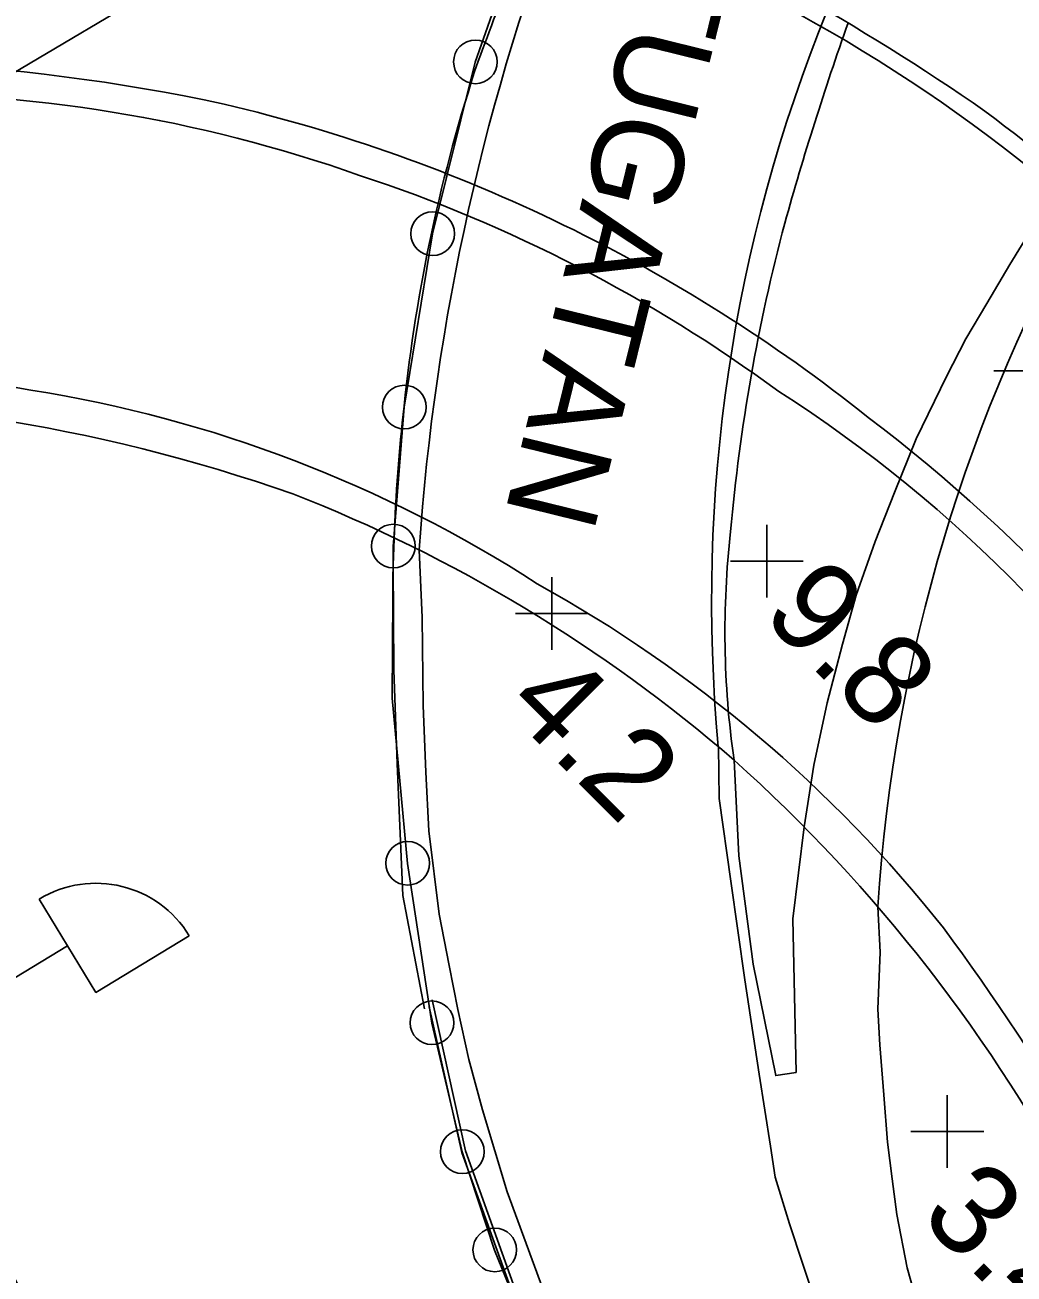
# Model space of a CAD drawing. Extents: x 1596643 to 1597288, y 13057194 to 13057957.
# Drawn here: x 1596899.03 to 1596926.19, y 13057506.23 to 13057540.55 of the extents above; entities that cross this region are included whole.
import ezdxf

# ---------------------------------------------------------------- set-up
doc = ezdxf.new("R2010")
doc.units = 0
for name, color, linetype in [('A spårmitt L', 7, 'Continuous'), ('BAS bro ej def L', 7, 'Continuous'), ('BAS byggnad anläggning L', 7, 'Continuous'), ('BAS gränspunkt P', 7, 'Continuous'), ('BAS Level 16', 7, 'Continuous'), ('BAS Level 37', 7, 'Continuous'), ('BAS markytetext T', 7, 'Continuous'), ('BAS stödmur fot L', 7, 'Continuous'), ('BAS stödmur krön L', 7, 'Continuous'), ('BAS väg T', 7, 'Continuous'), ('BAS vägbanekant L', 7, 'Continuous'), ('BAS vägbanekant skymd L', 7, 'Continuous'), ('F dvärgsignal fristående P', 7, 'Continuous')]:
    doc.layers.add(name, color=color, linetype=linetype)

msp = doc.modelspace()

# ---------------------------------------------------------------- linework, layer by layer
at = {"layer": 'A spårmitt L'}
msp.add_arc((1596499.999, 13057297.54), 450, 26.52378, 31.49284, dxfattribs=at)
at = {"layer": 'BAS bro ej def L'}
for points in [[(1596927.617, 13057536.425), (1596927.142, 13057535.659), (1596926.643, 13057534.893), (1596926.072, 13057533.965), (1596925.438, 13057532.896), (1596924.866, 13057531.928), (1596924.333, 13057530.888), (1596923.497, 13057529.181), (1596922.908, 13057527.705), (1596922.372, 13057526.36), (1596921.854, 13057524.883), (1596921.48, 13057523.536), (1596921.052, 13057521.926), (1596920.693, 13057520.212), (1596920.425, 13057518.517)], [(1596910.003, 13057513.523), (1596909.405, 13057516.629), (1596909.251, 13057520.25), (1596909.154, 13057522.833), (1596909.142, 13057525.719), (1596909.171, 13057526.423)], [(1596920.425, 13057518.517), (1596920.118, 13057515.992), (1596920.204, 13057511.773), (1596919.643, 13057511.688), (1596919.024, 13057514.746), (1596918.627, 13057517.719), (1596918.5, 13057520.353)]]:
    msp.add_lwpolyline(points, dxfattribs=at)
for centre, radius, start, end in [((1596821.119, 13057574.061), 96.719, 339.09659, 342.37079), ((1596886.889, 13057482.558), 67.647, 55.31245, 65.92546), ((1597000.567, 13057512.676), 83.732, 160.51681, 164.46611), ((1596954.451, 13057525.38), 45.256, 161.7492, 174.0477), ((1596888.315, 13057488.847), 61.711, 42.99724, 53.07755), ((1596968.043, 13057522.271), 49.829, 165.0805, 174.9779), ((1596890.993, 13057483.825), 46.464, 70.6568, 91.8562), ((1596950.183, 13057525.231), 41.03, 173.2226, 178.3352), ((1596891.219, 13057488.848), 41.675, 49.1099, 68.6622), ((1596942.795, 13057523.859), 24.546, 173.5111, 188.2116), ((1596889.308, 13057487.815), 43.714, 27.5921, 48.1026)]:
    msp.add_arc(centre, radius, start, end, dxfattribs=at)
at = {"layer": 'BAS byggnad anläggning L'}
msp.add_lwpolyline([(1596898.432, 13057539.054), (1596902.944, 13057541.738), (1596899.196, 13057548.047)], dxfattribs=at)
at = {"layer": 'BAS gränspunkt P'}
for centre, radius in [((1596911.398, 13057539.533), 0.6), ((1596911.398, 13057539.533), 0.6), ((1596911.393, 13057539.526), 0.001), ((1596911.393, 13057539.526), 0.001), ((1596910.225, 13057534.813), 0.6), ((1596910.225, 13057534.813), 0.6), ((1596910.22, 13057534.806), 0.001), ((1596910.22, 13057534.806), 0.001), ((1596909.448, 13057530.05), 0.6), ((1596909.448, 13057530.05), 0.6), ((1596909.443, 13057530.043), 0.001), ((1596909.443, 13057530.043), 0.001), ((1596909.144, 13057526.231), 0.6), ((1596909.144, 13057526.231), 0.6), ((1596909.139, 13057526.224), 0.001), ((1596909.139, 13057526.224), 0.001), ((1596909.536, 13057517.519), 0.6), ((1596909.536, 13057517.519), 0.6), ((1596909.531, 13057517.512), 0.001), ((1596909.531, 13057517.512), 0.001), ((1596910.204, 13057513.136), 0.6), ((1596910.204, 13057513.136), 0.6), ((1596910.199, 13057513.129), 0.001), ((1596910.199, 13057513.129), 0.001), ((1596911.04, 13057509.595), 0.6), ((1596911.04, 13057509.595), 0.6), ((1596911.035, 13057509.588), 0.001), ((1596911.035, 13057509.588), 0.001), ((1596911.93, 13057506.898), 0.6), ((1596911.93, 13057506.898), 0.6), ((1596911.925, 13057506.891), 0.001), ((1596911.925, 13057506.891), 0.001)]:
    msp.add_circle(centre, radius, dxfattribs=at)
at = {"layer": 'BAS Level 16'}
for p, q in [((1596926.629, 13057531.041), (1596925.629, 13057531.041)), ((1596926.629, 13057531.041), (1596925.629, 13057531.041)), ((1596919.398, 13057525.816), (1596919.398, 13057526.816)), ((1596919.398, 13057525.816), (1596919.398, 13057526.816)), ((1596919.398, 13057525.816), (1596918.398, 13057525.816)), ((1596919.398, 13057525.816), (1596918.398, 13057525.816)), ((1596919.398, 13057525.816), (1596920.398, 13057525.816)), ((1596919.398, 13057525.816), (1596919.398, 13057524.816)), ((1596919.398, 13057525.816), (1596920.398, 13057525.816)), ((1596919.398, 13057525.816), (1596919.398, 13057524.816)), ((1596913.498, 13057524.379), (1596913.498, 13057525.379)), ((1596913.498, 13057524.379), (1596913.498, 13057525.379)), ((1596913.498, 13057524.379), (1596912.498, 13057524.379)), ((1596913.498, 13057524.379), (1596912.498, 13057524.379)), ((1596913.498, 13057524.379), (1596914.498, 13057524.379)), ((1596913.498, 13057524.379), (1596913.498, 13057523.379)), ((1596913.498, 13057524.379), (1596914.498, 13057524.379)), ((1596913.498, 13057524.379), (1596913.498, 13057523.379)), ((1596924.355, 13057510.15), (1596924.355, 13057511.15)), ((1596924.355, 13057510.15), (1596924.355, 13057511.15)), ((1596924.355, 13057510.15), (1596923.355, 13057510.15)), ((1596924.355, 13057510.15), (1596923.355, 13057510.15)), ((1596924.355, 13057510.15), (1596925.355, 13057510.15)), ((1596924.355, 13057510.15), (1596924.355, 13057509.15)), ((1596924.355, 13057510.15), (1596925.355, 13057510.15)), ((1596924.355, 13057510.15), (1596924.355, 13057509.15))]:
    msp.add_line(p, q, dxfattribs=at)
at = {"layer": 'BAS Level 37'}
for points in [[(1596911.392, 13057539.526), (1596912.764, 13057543.432)], [(1596910.219, 13057534.806), (1596911.392, 13057539.526)], [(1596909.442, 13057530.043), (1596910.219, 13057534.806)], [(1596909.138, 13057526.224), (1596909.442, 13057530.043)], [(1596909.116, 13057522.057), (1596909.138, 13057526.224)], [(1596909.53, 13057517.512), (1596909.116, 13057522.057)], [(1596910.198, 13057513.129), (1596909.53, 13057517.512)], [(1596911.034, 13057509.588), (1596910.198, 13057513.129)], [(1596911.924, 13057506.891), (1596911.034, 13057509.588)], [(1596913.771, 13057502.349), (1596911.924, 13057506.891)]]:
    msp.add_lwpolyline(points, dxfattribs=at)
at = {"layer": 'BAS stödmur fot L'}
msp.add_lwpolyline([(1596910.126, 13057513.576), (1596911.022, 13057509.574), (1596912.93, 13057504.288), (1596915.996, 13057497.063), (1596921.012, 13057486.902), (1596925.938, 13057476.979), (1596929.942, 13057468.896)], dxfattribs=at)
at = {"layer": 'BAS stödmur krön L'}
msp.add_lwpolyline([(1596910.214, 13057513.767), (1596911.127, 13057509.619), (1596913.141, 13057503.998), (1596916.093, 13057497.121), (1596921.06, 13057486.966), (1596925.519, 13057477.89), (1596930.551, 13057467.911), (1596935.677, 13057457.761), (1596940.017, 13057449.129), (1596943.748, 13057442.095)], dxfattribs=at)
at = {"layer": 'BAS vägbanekant L'}
for points in [[(1596909.852, 13057526.126), (1596909.933, 13057524.265), (1596909.962, 13057521.856), (1596910.034, 13057520.017), (1596910.117, 13057518.411), (1596910.4, 13057516.123), (1596910.678, 13057514.709), (1596910.915, 13057513.499), (1596911.213, 13057512.126), (1596911.593, 13057510.742), (1596912.272, 13057508.493), (1596913.245, 13057505.826), (1596914.218, 13057503.383), (1596915.393, 13057500.633), (1596917.977, 13057495.093), (1596921.539, 13057487.973), (1596925.462, 13057480.018), (1596929.708, 13057471.482), (1596935.948, 13057459.15)], [(1596923.603, 13057500.34), (1596922.301, 13057502.145), (1596921.757, 13057502.991), (1596921.245, 13057504.334), (1596920.793, 13057505.302), (1596920.382, 13057506.533), (1596920.022, 13057507.612), (1596919.632, 13057508.894), (1596919.504, 13057509.749), (1596919.189, 13057511.721), (1596918.795, 13057514.315), (1596918.413, 13057517.029), (1596918.089, 13057519.297), (1596918.068, 13057520.722)], [(1596922.45, 13057516.319), (1596922.508, 13057515.079), (1596922.45, 13057513.514), (1596922.506, 13057512.529), (1596922.611, 13057511.156), (1596922.716, 13057509.855), (1596922.843, 13057508.849), (1596922.97, 13057507.872), (1596923.257, 13057506.408), (1596923.557, 13057505.329), (1596924.037, 13057503.803), (1596924.348, 13057503.039), (1596924.918, 13057501.238)]]:
    msp.add_lwpolyline(points, dxfattribs=at)
for centre, radius, start, end in [((1596899.166, 13057502.372), 43.887, 48.4408, 70.1546), ((1596893.232, 13057485.798), 53.769, 77.9076, 96.8735), ((1596895.129, 13057499.432), 39.231, 70.5134, 91.0268), ((1596894.196, 13057494.737), 44.836, 51.3717, 76.7191), ((1596895.379, 13057497.396), 41.077, 53.6431, 71.7896), ((1596892.758, 13057494.11), 36.969, 79.9774, 103.157), ((1596893.589, 13057495.036), 35.918, 57.1015, 81.0257), ((1596899.727, 13057499.138), 37.179, 30.737, 57.4508), ((1596895.501, 13057494.499), 44.223, 31.4886, 52.8852), ((1596895.128, 13057492.692), 37.139, 38.3613, 61.0623), ((1596871.537, 13057476.711), 65.589, 24.1774, 36.51768)]:
    msp.add_arc(centre, radius, start, end, dxfattribs=at)
at = {"layer": 'BAS vägbanekant skymd L'}
for centre, radius, start, end in [((1596972.367, 13057521.809), 62.664, 158.75177, 176.0506), ((1596960.949, 13057524.71), 43.067, 157.8594, 185.3133), ((1596967.74, 13057513.421), 45.383, 150.3688, 176.3388)]:
    msp.add_arc(centre, radius, start, end, dxfattribs=at)
at = {"layer": 'F dvärgsignal fristående P'}
msp.add_line((1596900.199, 13057515.251), (1596898.275, 13057514.084), dxfattribs=at)
msp.add_line((1596900.199, 13057515.251), (1596898.275, 13057514.084), dxfattribs=at)
msp.add_lwpolyline([(1596899.42, 13057516.534), (1596900.977, 13057513.969), (1596903.541, 13057515.525)], dxfattribs=at)
msp.add_lwpolyline([(1596899.42, 13057516.534), (1596900.977, 13057513.969), (1596903.541, 13057515.525)], dxfattribs=at)
msp.add_arc((1596900.977, 13057513.969), 3, 31.2494, 121.2494, dxfattribs=at)
msp.add_arc((1596900.977, 13057513.969), 3, 31.2494, 121.2494, dxfattribs=at)

# ---------------------------------------------------------------- texts
at = {"layer": 'BAS markytetext T'}
for s, p in [('9.8', (1596919.214, 13057524.311)), ('4.2', (1596912.147, 13057521.798)), ('3.4', (1596923.553, 13057507.781))]:
    msp.add_text(s, height=2.5, rotation=315, dxfattribs=at).set_placement(p)
at = {"layer": 'BAS väg T'}
msp.add_text('VATTUGATAN', height=2.5, rotation=256.14, dxfattribs=at).set_placement((1596917.586, 13057548.963))

doc.saveas('drawing.dxf')
